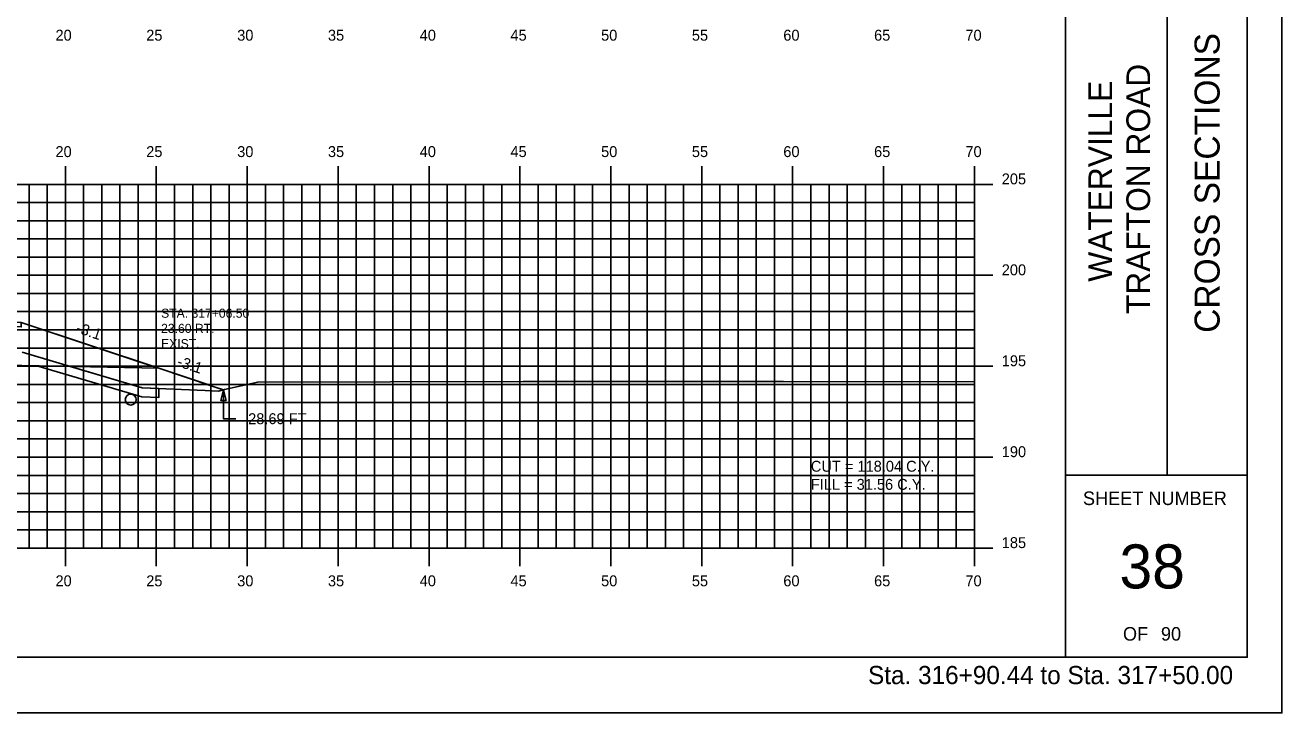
# Model space of a CAD drawing. Extents: x 1138985 to 1139155, y 608981 to 609091.
# Drawn here: x 1139085.7 to 1139154.9, y 608981.3 to 609019.1 of the extents above; entities that cross this region are included whole.
import ezdxf

# ---------------------------------------------------------------- set-up
doc = ezdxf.new("R2010")
doc.units = 0
for name, color, linetype in [('ANNOTATION', 7, 'Continuous'), ('BORDER', 7, 'Continuous'), ('D_Roadway_SlopeLines', 7, 'Continuous'), ('D_Roadway_SubGrade', 7, 'Continuous'), ('D_Text_Monospaced', 7, 'Continuous'), ('D_Text_Standard', 7, 'Continuous'), ('H_V ANNOTATION', 7, 'Continuous'), ('HIGHWAY_TITLE', 7, 'Continuous'), ('MAJOR', 7, 'Continuous'), ('MINOR', 7, 'Continuous'), ('PLOT BOUNDARY', 7, 'Continuous'), ('S_Drainage_Invert', 7, 'Continuous'), ('S_Roadway_Centerline', 7, 'Continuous'), ('SHADING', 7, 'Continuous')]:
    doc.layers.add(name, color=color, linetype=linetype)

msp = doc.modelspace()

# ---------------------------------------------------------------- linework, layer by layer
msp.add_lwpolyline([(1139032.35, 609001.237), (1139049.597, 609002.617), (1139051.949, 609002.805), (1139056.349, 609002.981), (1139056.949, 609003.005), (1139066.629, 609003.198), (1139067.949, 609003.225), (1139077.629, 609003.031), (1139078.949, 609003.005), (1139084.726, 609002.774), (1139085.52, 609002.742), (1139092.173, 609000.524), (1139093.079, 609000.222), (1139095.719, 608999.342), (1139096.079, 608999.222), (1139096.573, 608999.058), (1139096.638, 608999.036)])
at = {"layer": 'BORDER'}
for p, q in [((1139142.949, 608984.335), (1139142.949, 609089.335)), ((1139148.54, 608994.338), (1139148.54, 609029.338)), ((1139142.949, 608994.338), (1139152.949, 608994.338))]:
    msp.add_line(p, q, dxfattribs=at)
msp.add_lwpolyline([(1138992.949, 608984.335), (1139152.949, 608984.335), (1139152.949, 609089.335), (1138992.949, 609089.335)], close=True, dxfattribs=at)
at = {"layer": 'D_Roadway_SlopeLines'}
for points in [[(1139093.079, 608999.107), (1139093.079, 608998.607), (1139092.151, 608998.645), (1139086.385, 609000.356)], [(1139093.079, 609000.222), (1139096.079, 608999.222)], [(1139096.079, 608999.222), (1139096.638, 608999.036)]]:
    msp.add_lwpolyline(points, dxfattribs=at)
at = {"layer": 'D_Roadway_SubGrade'}
msp.add_lwpolyline([(1139078.949, 609002.588), (1139078.949, 609002.755), (1139085.52, 609002.492), (1139085.52, 609002.742), (1139085.52, 609002.742), (1139093.079, 609000.222), (1139078.949, 609000.505)], close=True, dxfattribs=at)
at = {"layer": 'D_Text_Standard'}
msp.add_lwpolyline([(1139096.638, 608999.036), (1139096.784, 608998.454), (1139096.493, 608998.454)], close=True, dxfattribs=at)
msp.add_lwpolyline([(1139096.638, 608999.036), (1139096.64, 608997.449), (1139097.32, 608997.449)], dxfattribs=at)
at = {"layer": 'MAJOR'}
for p, q in [((1139087.949, 609011.337), (1139087.949, 609010.335)), ((1139092.949, 609011.337), (1139092.949, 609010.335)), ((1139097.949, 609011.337), (1139097.949, 609010.335)), ((1139102.949, 609011.337), (1139102.949, 609010.335)), ((1139107.949, 609011.337), (1139107.949, 609010.335)), ((1139112.949, 609011.337), (1139112.949, 609010.335)), ((1139117.949, 609011.337), (1139117.949, 609010.335)), ((1139122.949, 609011.337), (1139122.949, 609010.335)), ((1139127.949, 609011.337), (1139127.949, 609010.335)), ((1139132.949, 609011.337), (1139132.949, 609010.335)), ((1139137.949, 609011.337), (1139137.949, 609010.335)), ((1138997.949, 609010.335), (1139137.949, 609010.335)), ((1138997.949, 609010.335), (1139137.949, 609010.335)), ((1139087.949, 608990.335), (1139087.949, 609010.335)), ((1139092.949, 608990.335), (1139092.949, 609010.335)), ((1139097.949, 608990.335), (1139097.949, 609010.335)), ((1139102.949, 608990.335), (1139102.949, 609010.335)), ((1139107.949, 608990.335), (1139107.949, 609010.335)), ((1139112.949, 608990.335), (1139112.949, 609010.335)), ((1139117.949, 608990.335), (1139117.949, 609010.335)), ((1139122.949, 608990.335), (1139122.949, 609010.335)), ((1139127.949, 608990.335), (1139127.949, 609010.335)), ((1139132.949, 608990.335), (1139132.949, 609010.335)), ((1139138.951, 609010.335), (1139136.947, 609010.335)), ((1139137.949, 608990.335), (1139137.949, 609010.335)), ((1139137.949, 608990.335), (1139137.949, 609010.335)), ((1138997.949, 609005.335), (1139137.949, 609005.335)), ((1139138.951, 609005.335), (1139136.947, 609005.335)), ((1138997.949, 609000.335), (1139137.949, 609000.335)), ((1139138.951, 609000.335), (1139136.947, 609000.335)), ((1138997.949, 608995.335), (1139137.949, 608995.335)), ((1139138.951, 608995.335), (1139136.947, 608995.335)), ((1138997.949, 608990.335), (1139137.949, 608990.335)), ((1138997.949, 608990.335), (1139137.949, 608990.335)), ((1139087.949, 608989.333), (1139087.949, 608990.335)), ((1139092.949, 608989.333), (1139092.949, 608990.335)), ((1139097.949, 608989.333), (1139097.949, 608990.335)), ((1139102.949, 608989.333), (1139102.949, 608990.335)), ((1139107.949, 608989.333), (1139107.949, 608990.335)), ((1139112.949, 608989.333), (1139112.949, 608990.335)), ((1139117.949, 608989.333), (1139117.949, 608990.335)), ((1139122.949, 608989.333), (1139122.949, 608990.335)), ((1139127.949, 608989.333), (1139127.949, 608990.335)), ((1139132.949, 608989.333), (1139132.949, 608990.335)), ((1139138.951, 608990.335), (1139136.947, 608990.335)), ((1139137.949, 608989.333), (1139137.949, 608990.335))]:
    msp.add_line(p, q, dxfattribs=at)
at = {"layer": 'MINOR'}
for p, q in [((1139085.949, 608990.335), (1139085.949, 609010.335)), ((1139086.949, 608990.335), (1139086.949, 609010.335)), ((1139088.949, 608990.335), (1139088.949, 609010.335)), ((1139089.949, 608990.335), (1139089.949, 609010.335)), ((1139090.949, 608990.335), (1139090.949, 609010.335)), ((1139091.949, 608990.335), (1139091.949, 609010.335)), ((1139093.949, 608990.335), (1139093.949, 609010.335)), ((1139094.949, 608990.335), (1139094.949, 609010.335)), ((1139095.949, 608990.335), (1139095.949, 609010.335)), ((1139096.949, 608990.335), (1139096.949, 609010.335)), ((1139098.949, 608990.335), (1139098.949, 609010.335)), ((1139099.949, 608990.335), (1139099.949, 609010.335)), ((1139100.949, 608990.335), (1139100.949, 609010.335)), ((1139101.949, 608990.335), (1139101.949, 609010.335)), ((1139103.949, 608990.335), (1139103.949, 609010.335)), ((1139104.949, 608990.335), (1139104.949, 609010.335)), ((1139105.949, 608990.335), (1139105.949, 609010.335)), ((1139106.949, 608990.335), (1139106.949, 609010.335)), ((1139108.949, 608990.335), (1139108.949, 609010.335)), ((1139109.949, 608990.335), (1139109.949, 609010.335)), ((1139110.949, 608990.335), (1139110.949, 609010.335)), ((1139111.949, 608990.335), (1139111.949, 609010.335)), ((1139113.949, 608990.335), (1139113.949, 609010.335)), ((1139114.949, 608990.335), (1139114.949, 609010.335)), ((1139115.949, 608990.335), (1139115.949, 609010.335)), ((1139116.949, 608990.335), (1139116.949, 609010.335)), ((1139118.949, 608990.335), (1139118.949, 609010.335)), ((1139119.949, 608990.335), (1139119.949, 609010.335)), ((1139120.949, 608990.335), (1139120.949, 609010.335)), ((1139121.949, 608990.335), (1139121.949, 609010.335)), ((1139123.949, 608990.335), (1139123.949, 609010.335)), ((1139124.949, 608990.335), (1139124.949, 609010.335)), ((1139125.949, 608990.335), (1139125.949, 609010.335)), ((1139126.949, 608990.335), (1139126.949, 609010.335)), ((1139128.949, 608990.335), (1139128.949, 609010.335)), ((1139129.949, 608990.335), (1139129.949, 609010.335)), ((1139130.949, 608990.335), (1139130.949, 609010.335)), ((1139131.949, 608990.335), (1139131.949, 609010.335)), ((1139133.949, 608990.335), (1139133.949, 609010.335)), ((1139134.949, 608990.335), (1139134.949, 609010.335)), ((1139135.949, 608990.335), (1139135.949, 609010.335)), ((1139136.949, 608990.335), (1139136.949, 609010.335)), ((1138997.949, 609009.335), (1139137.949, 609009.335)), ((1139137.949, 609009.335), (1139136.947, 609009.335)), ((1138997.949, 609008.335), (1139137.949, 609008.335)), ((1139137.949, 609008.335), (1139136.947, 609008.335)), ((1138997.949, 609007.335), (1139137.949, 609007.335)), ((1139137.949, 609007.335), (1139136.947, 609007.335)), ((1138997.949, 609006.335), (1139137.949, 609006.335)), ((1139137.949, 609006.335), (1139136.947, 609006.335)), ((1138997.949, 609004.335), (1139137.949, 609004.335)), ((1139137.949, 609004.335), (1139136.947, 609004.335)), ((1138997.949, 609003.335), (1139137.949, 609003.335)), ((1139137.949, 609003.335), (1139136.947, 609003.335)), ((1138997.949, 609002.335), (1139137.949, 609002.335)), ((1139137.949, 609002.335), (1139136.947, 609002.335)), ((1138997.949, 609001.335), (1139137.949, 609001.335)), ((1139137.949, 609001.335), (1139136.947, 609001.335)), ((1138997.949, 608999.335), (1139137.949, 608999.335)), ((1139137.949, 608999.335), (1139136.947, 608999.335)), ((1138997.949, 608998.335), (1139137.949, 608998.335)), ((1139137.949, 608998.335), (1139136.947, 608998.335)), ((1138997.949, 608997.335), (1139137.949, 608997.335)), ((1139137.949, 608997.335), (1139136.947, 608997.335)), ((1138997.949, 608996.335), (1139137.949, 608996.335)), ((1139137.949, 608996.335), (1139136.947, 608996.335)), ((1138997.949, 608994.335), (1139137.949, 608994.335)), ((1139137.949, 608994.335), (1139136.947, 608994.335)), ((1138997.949, 608993.335), (1139137.949, 608993.335)), ((1139137.949, 608993.335), (1139136.947, 608993.335)), ((1138997.949, 608992.335), (1139137.949, 608992.335)), ((1139137.949, 608992.335), (1139136.947, 608992.335)), ((1138997.949, 608991.335), (1139137.949, 608991.335)), ((1139137.949, 608991.335), (1139136.947, 608991.335))]:
    msp.add_line(p, q, dxfattribs=at)
at = {"layer": 'PLOT BOUNDARY'}
msp.add_lwpolyline([(1138984.856, 608981.276), (1139154.856, 608981.276), (1139154.856, 609091.276), (1138984.856, 609091.276)], close=True, dxfattribs=at)
at = {"layer": 'S_Drainage_Invert'}
msp.add_circle((1139091.545, 608998.502), 0.3, dxfattribs=at)
at = {"layer": 'S_Roadway_Centerline'}
msp.add_lwpolyline([(1139085.575, 609001.102), (1139092.172, 608999.144), (1139095.637, 608999.001), (1139096.369, 608998.96), (1139096.699, 608999.054), (1139098.531, 608999.462), (1139113.131, 608999.502), (1139127.448, 608999.492), (1139137.949, 608999.473)], dxfattribs=at)
at = {"layer": 'SHADING'}
msp.add_line((1139088.211, 609000.319), (1139086.385, 609000.356), dxfattribs=at)
for points in [[(1139086.385, 609000.356), (1139092.151, 608998.645), (1139093.079, 608998.607), (1139093.079, 608999.107)], [(1139093.079, 608999.107), (1139092.172, 608999.144), (1139088.211, 609000.319)]]:
    msp.add_lwpolyline(points, dxfattribs=at)

# ---------------------------------------------------------------- texts
at = {"layer": 'ANNOTATION'}
for rotation, p in [(341.56528, (1139088.496, 609002.204)), (341.56505, (1139094.049, 609000.353))]:
    msp.add_text('-3:1', height=0.6, rotation=rotation, dxfattribs=at).set_placement(p)
at = {"layer": 'BORDER'}
msp.add_text('CROSS SECTIONS', height=1.37787, rotation=90, dxfattribs=at).set_placement((1139151.433, 609002.172))
for s, height, p in [('SHEET NUMBER', 0.74527, (1139143.914, 608992.701)), ('38', 2.4194, (1139145.924, 608988.118)), ('OF', 0.7453, (1139146.116, 608985.248)), ('90', 0.7453, (1139148.205, 608985.248))]:
    msp.add_text(s, height=height, dxfattribs=at).set_placement(p)
at = {"layer": 'D_Text_Monospaced'}
for s, height, p in [('STA. 317+06.50', 0.49998, (1139093.212, 609003)), ('23.60 RT.', 0.5, (1139093.212, 609002.166)), ('EXIST. ', 0.5, (1139093.212, 609001.326))]:
    msp.add_text(s, height=height, dxfattribs=at).set_placement(p)
at = {"layer": 'D_Text_Standard'}
for s, p in [('28.69 FT', (1139098, 608997.149)), ('CUT = 118.04 C.Y.', (1139128.949, 608994.535)), ('FILL = 31.56 C.Y.', (1139128.949, 608993.539))]:
    msp.add_text(s, height=0.6, dxfattribs=at).set_placement(p)
at = {"layer": 'H_V ANNOTATION'}
for s, height, p in [('20', 0.6, (1139087.403, 609018.235)), ('25', 0.6, (1139092.395, 609018.235)), ('30', 0.6, (1139097.397, 609018.235)), ('35', 0.6, (1139102.389, 609018.235)), ('40', 0.6, (1139107.435, 609018.235)), ('45', 0.6, (1139112.427, 609018.235)), ('50', 0.6, (1139117.413, 609018.235)), ('55', 0.6, (1139122.405, 609018.235)), ('60', 0.6, (1139127.435, 609018.235)), ('65', 0.6, (1139132.427, 609018.235)), ('70', 0.6, (1139137.451, 609018.235)), ('20', 0.6, (1139087.403, 609011.835)), ('25', 0.6, (1139092.395, 609011.835)), ('30', 0.6, (1139097.397, 609011.835)), ('35', 0.6, (1139102.389, 609011.835)), ('40', 0.6, (1139107.435, 609011.835)), ('45', 0.6, (1139112.427, 609011.835)), ('50', 0.6, (1139117.413, 609011.835)), ('55', 0.6, (1139122.405, 609011.835)), ('60', 0.6, (1139127.435, 609011.835)), ('65', 0.6, (1139132.427, 609011.835)), ('70', 0.6, (1139137.451, 609011.835)), ('205', 0.6, (1139139.449, 609010.335)), ('200', 0.6, (1139139.449, 609005.335)), ('195', 0.6, (1139139.449, 609000.335)), ('190', 0.6, (1139139.449, 608995.335)), ('185', 0.6, (1139139.449, 608990.335)), ('20', 0.6, (1139087.403, 608988.235)), ('25', 0.6, (1139092.395, 608988.235)), ('30', 0.6, (1139097.397, 608988.235)), ('35', 0.6, (1139102.389, 608988.235)), ('40', 0.6, (1139107.435, 608988.235)), ('45', 0.6, (1139112.427, 608988.235)), ('50', 0.6, (1139117.413, 608988.235)), ('55', 0.6, (1139122.405, 608988.235)), ('60', 0.6, (1139127.435, 608988.235)), ('65', 0.6, (1139132.427, 608988.235)), ('70', 0.6, (1139137.451, 608988.235)), ('Sta. 316+90.44 to Sta. 317+50.00', 1.0002, (1139132.095, 608982.855))]:
    msp.add_text(s, height=height, dxfattribs=at).set_placement(p)
at = {"layer": 'HIGHWAY_TITLE'}
for s, height, p in [('TRAFTON ROAD', 1.30428, (1139147.608, 609003.201)), ('WATERVILLE', 1.3043, (1139145.521, 609004.98))]:
    msp.add_text(s, height=height, rotation=90, dxfattribs=at).set_placement(p)

doc.saveas('drawing.dxf')
